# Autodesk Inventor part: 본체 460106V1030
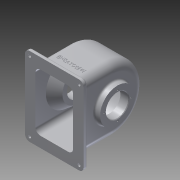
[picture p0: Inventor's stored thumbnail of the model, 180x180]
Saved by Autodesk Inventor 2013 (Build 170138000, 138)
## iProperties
Created: 2016-01
Part Number: 본체 460106V1030
Material: 알루미늄 6061
Document SubType Name: Modeling
Designer: Administrator
Density: 1 g/cm^3
Author: Administrator
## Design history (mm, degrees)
sketch "스케치1"
  geometry: L1 (-44, 70)-(44, 70); L2 (52, 62)-(52, -62); L3 (44, -70)-(-44, -70); L4 (-52, -62)-(-52, 62); C1 r 2.5 at (-44, 62); C2 r 2.5 at (44, 62); C3 r 2.5 at (-44, -62); C4 r 2.5 at (44, -62); A1 r 8 centre (-44, 62) between (-44, 70) and (-52, 62); A2 r 8 centre (-44, -62) between (-52, -62) and (-44, -70); A3 r 8 centre (44, -62) between (44, -70) and (52, -62); A4 r 8 centre (44, 62) between (52, 62) and (44, 70); 6 further points
  constraints: 8 centre point, 8 end point, 8 point on circle, 8 tangent, 6 point on line, 4 coincident, 3 equal radius, 2 midpoint, 2 parallel, 1 horizontal, 1 horizontal alignment, 1 perpendicular, 1 vertical alignment
  dimensions: "d0" = 104 distance of point (52, -70) point (-52, -70); "d1" = 140 distance of point (52, 70) point (52, -70); "d2" = 8 radius of A1; "d3" = 5 diameter of C1; "d4" = 5 diameter of C2; "d5" = 5 diameter of C3; "d6" = 5 diameter of C4
extrude "돌출1" new body sketch "스케치1" distance "d7" = 7; taper "d8" = 0 deg
node "작업 평면1"
sketch "스케치2"
  geometry: L1 (132, 7)-(132, 0) reference; L2 (132, 0)-(-8, 0) reference; L3 (-8, 0)-(-8, 7) reference; L4 (-8, 7)-(132, 7) reference; L5 (62, 0)-(62, 64); L6 (5, 64)-(5, 3.5); L7 (119, 64)-(119, 3.5); L8 (5, 3.5)-(119, 3.5); A1 r 57 centre (62, 64) between (119, 64) and (5, 64)
  constraints: 8 end point, 3 tangent, 2 parallel, 2 perpendicular, 2 point on circle, 1 centre point, 1 coincident
  dimensions: "d9" = 64 distance of L5.start L5.end; "d13" = 3.5 distance between parallel lines of L2 L8
extrude "돌출2" join sketch "스케치2" stored distance "d14" = 77; taper "d15" = 0 deg
sketch "스케치3"
  geometry: L1 (132, 7)-(132, 0) reference; L2 (132, 0)-(-8, 0) reference; L3 (-8, 0)-(-8, 7) reference; L4 (-8, 7)-(5, 7) reference; L5 (5, 7)-(5, 64) reference; L6 (119, 64)-(119, 7) reference; L7 (119, 7)-(132, 7) reference; L8 (62, 0)-(62, 64); L9 (11, 0)-(113, 0); L10 (11, 64)-(11, 0); L11 (113, 64)-(113, 0); A1 r 57 centre (62, 64) between (119, 64) and (5, 64) reference; A2 r 51 centre (62, 64) between (113, 64) and (11, 64); 1 further point
  constraints: 8 end point, 2 midpoint, 2 perpendicular, 2 point on circle, 2 tangent, 1 centre point, 1 coincident
  dimensions: "d17" = 64 distance of L8.start L8.end (derived); "d19" = 51 radius of A2; "d20" = 102 distance of L9.start L9.end
extrude "돌출3" cut sketch "스케치3" stored distance "d21" = 67; taper "d22" = 0 deg
node "작업 평면2"
sketch "스케치4"
  geometry: L1 (90.5, 0)-(90.5, -7) reference; L2 (90.5, -7)-(72, -7) reference; L3 (72, -7)-(72, 108) reference; L4 (72, 108)-(5, 108) reference; L5 (5, 108)-(5, -7) reference; L6 (5, -7)-(-13.5, -7) reference; L7 (-13.5, -7)-(-13.5, 0) reference; L8 (-13.5, 0)-(0, 0) reference; L9 (0, 0)-(0, 114) reference; L10 (0, 114)-(77, 114) reference; L11 (77, 114)-(77, 0) reference; L12 (77, 0)-(90.5, 0) reference; L13 (5, -7)-(5, 53); L14 (5, 53)-(21, 53); L15 (21, 53)-(21, 81); L16 (21, 81)-(3.132, 95.993); L17 (3.132, 95.993)-(3.132, 53); L18 (3.132, 53)-(5, 53); 1 further point
  constraints: 12 end point, 3 perpendicular, 1 parallel, 1 point on line
  dimensions: "d23" = 60 distance of L5.end L13.end; "d24" = 16 distance of L13.end L14.end; "d25" = 28 distance of L14.end L15.end; "d26" = 50 deg angle of L15 L16; "d27" = 1.86792 distance between parallel lines of L17 L5
revolve "회전1" sketch "스케치4" stored, may be unused: angle "d28" = 90 deg
sketch "스케치8"
  geometry: L1 (132, 7)-(132, 0) reference; L2 (132, 0)-(-8, 0) reference; L3 (-8, 0)-(-8, 7) reference; L4 (-8, 7)-(5, 7) reference; L5 (5, 7)-(119, 7) reference; L6 (119, 7)-(132, 7) reference; L7 (5, 7)-(5, 64) reference; L8 (119, 64)-(119, 7) reference; C1 r 31 at (62, 64); A1 r 57 centre (62, 64) between (119, 64) and (5, 64) reference; 1 further point
  constraints: 1 centre point, 1 coincident
  dimensions: "d45" = 62 diameter of C1
extrude "돌출5" join sketch "스케치8" distance "d47" = 10; taper "d48" = 0 deg
sketch "스케치9"
  geometry: C1 r 31 at (0, 0) reference; A1 r 24 centre (0, 0) between (0, 24) and (-24, 0); 3 further points
  constraints: 4 point on circle, 1 centre point, 1 coincident
  dimensions: "d49" = 48 diameter of A1
hole "구멍2" sketch "스케치9" at (0, 24), (-24, 0), (0, -24), (24, 0) diameter "d50" = 2.459; stored, may be unused: countersink angle "d54" = 90 deg, drill point angle "d56" = 118 deg; dims "d51" = 6, "d52" = 4, "d53" = 2, "d55" = 8
sketch "스케치10"
  geometry: C1 r 31 at (0, 0) reference; C2 r 20 at (0, 0); 1 further point
  constraints: 1 centre point, 1 coincident
  dimensions: "d57" = 40 diameter of C2
extrude "돌출6" cut sketch "스케치10" distance "d59" = 20; taper "d60" = 0 deg
node "작업 평면3"
sketch "스케치11"
  geometry: C1 r 6 at (0, 0); 1 further point
  constraints: 1 centre point, 1 coincident
  dimensions: "d62" = 12 diameter of C1
extrude "돌출7" join sketch "스케치11" stored distance "d63" = 20; taper "d64" = 0 deg
sketch "스케치12"
  geometry: L1 (90.5, 0)-(90.5, -7) reference; L2 (90.5, -7)-(-13.5, -7) reference; L3 (-13.5, -7)-(-13.5, 0) reference; L4 (-13.5, 0)-(0, 0) reference; L5 (0, 0)-(77, 0) reference; L6 (77, 0)-(90.5, 0) reference; L7 (0, 0)-(0, 57) reference; L8 (0, 57)-(77, 57) reference; L9 (77, 57)-(77, 0) reference; L10 (90.5, 0)-(90.5, -7) reference; L11 (90.5, -7)-(-13.5, -7) reference; L12 (-13.5, -7)-(-13.5, 0) reference; L13 (-13.5, 0)-(0, 0) reference; L14 (0, 0)-(77, 0) reference; L15 (77, 0)-(90.5, 0) reference; L16 (0, 0)-(0, 57) reference; L17 (0, 57)-(77, 57) reference; L18 (77, 57)-(77, 0) reference; 2 further points
  constraints: 1 other
feature "엠보싱1" sketch "스케치12" dims "d0" = 104, "d1" = 140, "d2" = 8, "d3" = 5, "d4" = 5, "d5" = 5, "d6" = 5, "d68" = 0.5, "d69" = 0
fillet "모깎기1" dims "d70" = 3
fillet "모깎기3" dims "d72" = 9
fillet "모깎기4" dims "d73" = 3
fillet "모깎기5" dims "d74" = 3
fillet "모깎기6" dims "d75" = 14
fillet "모깎기7" dims "d76" = 1
chamfer "모따기1" distance "d78" = 1; stored, may be unused: second distance "d79" = 2, angle "d80" = 45 deg
hole "구멍3" diameter "d83" = 4.459; stored, may be unused: countersink angle "d87" = 90 deg, drill point angle "d89" = 118 deg; dims "d81" = 10, "d82" = 10, "d84" = 20, "d85" = 4, "d86" = 2, "d88" = 8
node "작업 평면4"
sketch "스케치13"
  geometry: L1 (-9, -45.426)-(-9, -64) reference; L2 (-9, -64)-(-27.5, -64) reference; L3 (-27.5, -64)-(-27.5, -60) reference; L4 (-24.5, -57)-(-15, -57) reference; L5 (-14, -56)-(-14, 43) reference; L6 (0, 57)-(15.5, 57) reference; L7 (18.5, 60)-(18.5, 63) reference; L8 (18.5, 63)-(22.271, 63) reference; L9 (22.271, 63)-(22.271, 51) reference; L10 (22.271, 51)-(0, 51) reference; L11 (-9, 42)-(-9, 37.426) reference; L12 (-9, 37.426)-(7, 24) reference; L13 (7, 24)-(7, -32) reference; L14 (7, -32)-(-9, -45.426) reference; L15 (65, -22.77)-(64.261, -24) reference; L16 (64.261, -24)-(65, -25.23) reference; L17 (65, -25.23)-(73, -25.23) reference; L18 (73, -25.23)-(73, -31) reference; L19 (73, -31)-(66, -31) reference; L20 (63, -34)-(63, -56) reference; L21 (64, -57)-(73.5, -57) reference; L22 (76.5, -60)-(76.5, -64) reference; L23 (76.5, -64)-(58, -64) reference; L24 (58, -64)-(58, -20) reference; L25 (58, -20)-(72, -20) reference; L26 (72, -20)-(73, -21) reference; L27 (73, -21)-(73, -22.77) reference; L28 (73, -22.77)-(65, -22.77) reference; L29 (65, 25.229)-(64.261, 24) reference; L30 (64.261, 24)-(65, 22.771) reference; L31 (65, 22.771)-(73, 22.771) reference; L32 (73, 22.771)-(73, 21) reference; L33 (73, 21)-(72, 20) reference; L34 (72, 20)-(58, 20) reference; L35 (58, 20)-(58, 42) reference; L36 (49, 51)-(26.73, 51) reference; L37 (26.73, 51)-(26.73, 63) reference; L38 (26.73, 63)-(30.5, 63) reference; L39 (30.5, 63)-(30.5, 60) reference; L40 (33.5, 57)-(49, 57) reference; L41 (63, 43)-(63, 34) reference; L42 (66, 31)-(73, 31) reference; L43 (73, 31)-(73, 25.229) reference; L44 (73, 25.229)-(65, 25.229) reference; L45 (-11, -40.577)-(-14, -43.094); L46 (-9, -45.426)-(-9, -64) reference; L47 (-9, -64)-(-27.5, -64) reference; L48 (-27.5, -64)-(-27.5, -60) reference; L49 (-24.5, -57)-(-15, -57) reference; L50 (-14, -56)-(-14, 43) reference; L51 (0, 57)-(15.5, 57) reference; L52 (18.5, 60)-(18.5, 63) reference; L53 (18.5, 63)-(22.271, 63) reference; L54 (22.271, 63)-(22.271, 51) reference; L55 (22.271, 51)-(0, 51) reference; L56 (-9, 42)-(-9, 37.426) reference; L57 (-9, 37.426)-(7, 24) reference; L58 (7, 24)-(7, -32) reference; L59 (7, -32)-(-9, -45.426) reference; L60 (65, -22.77)-(64.261, -24) reference; L61 (64.261, -24)-(65, -25.23) reference; L62 (65, -25.23)-(73, -25.23) reference; L63 (73, -25.23)-(73, -31) reference; L64 (73, -31)-(66, -31) reference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; A1 r 3 centre (-24.5, -60) between (-24.5, -57) and (-27.5, -60) reference; A2 r 1 centre (-15, -56) between (-15, -57) and (-14, -56) reference; A3 r 14 centre (0, 43) between (0, 57) and (-14, 43) reference; A4 r 9 centre (0, 42) between (0, 51) and (-9, 42) reference; A5 r 3 centre (66, -34) between (66, -31) and (63, -34) reference; A6 r 1 centre (64, -56) between (63, -56) and (64, -57) reference; A7 r 3 centre (73.5, -60) between (76.5, -60) and (73.5, -57) reference; A8 r 9 centre (49, 42) between (58, 42) and (49, 51) reference; A9 r 14 centre (49, 43) between (63, 43) and (49, 57) reference; A10 r 3 centre (66, 34) between (63, 34) and (66, 31) reference; A11 r 3 centre (-24.5, -60) between (-24.5, -57) and (-27.5, -60) reference; A12 r 1 centre (-15, -56) between (-15, -57) and (-14, -56) reference; A13 r 14 centre (0, 43) between (0, 57) and (-14, 43) reference; A14 r 9 centre (0, 42) between (0, 51) and (-9, 42) reference; A15 r 3 centre (66, -34) between (66, -31) and (63, -34) reference; A16 r 1 centre (64, -56) between (63, -56) and (64, -57) reference; A17 r 3 centre (73.5, -60) between (76.5, -60) and (73.5, -57) reference; A18 r 9 centre (49, 42) between (58, 42) and (49, 51) reference; A19 r 14 centre (49, 43) between (63, 43) and (49, 57) reference; A20 r 3 centre (66, 34) between (63, 34) and (66, 31) reference; 1 further point
  constraints: 10 end point, 2 perpendicular, 2 point on line, 4 other
  dimensions: "d90" = 5 distance between parallel lines of L14 L45; "d91" = 3 distance between parallel lines of L5 L92
revolve "회전3" sketch "스케치13" stored, may be unused: angle "d92" = 90 deg
sketch "스케치14"
  geometry: L1 (53.198, -53)-(67, -53) reference; L2 (70, -56)-(70, -60) reference; L3 (70, -60)-(-70, -60) reference; L4 (-70, -60)-(-70, -56) reference; L5 (-67, -53)-(-53.198, -53) reference; L6 (-51.66, -52)-(-51.66, 4) reference; L7 (51.66, 4)-(51.66, -52) reference; C1 r 36.577 at (0, 0) reference; A1 r 3 centre (67, -56) between (70, -56) and (67, -53) reference; A2 r 3 centre (-67, -56) between (-67, -53) and (-70, -56) reference; A3 r 51.66 centre (0, 4) between (51.66, 4) and (-51.66, 4) reference; A4 r 28 centre (0, 0) between (-28, 0) and (0, 28); 3 further points
  constraints: 4 point on circle, 1 centre point, 1 coincident, 2 other
  dimensions: "d93" = 56 diameter of A4
hole "구멍4" sketch "스케치14" at (-28, 0), (0, 28), (0, -28), (28, 0) diameter "d94" = 3.459; stored, may be unused: countersink angle "d98" = 90 deg, drill point angle "d100" = 118 deg; dims "d95" = 7, "d96" = 4, "d97" = 2, "d99" = 9
sketch "스케치15"
  geometry: C1 r 36.577 at (0, 0) reference; C2 r 20 at (0, 0); 1 further point
  constraints: 1 centre point, 1 coincident
  dimensions: "d101" = 40 diameter of C2
extrude "돌출8" cut sketch "스케치15" distance "d102" = 20; taper "d103" = 0 deg
chamfer "모따기2" distance "d104" = 1; stored, may be unused: second distance "d105" = 2, angle "d106" = 45 deg
fillet "모깎기9" dims "d107" = 3
node "솔리드1"
node "절단 모서리 투영1"
node "절단 모서리 투영2"
node "절단 모서리 투영3"
node "절단 모서리 투영5"
node "절단 모서리 투영6"
node "절단 모서리 투영7"
node "절단 모서리 투영8"
node "절단 모서리 투영9"
node "절단 모서리 투영10"
other parameters: "d11" = 57, "d61" = -127
